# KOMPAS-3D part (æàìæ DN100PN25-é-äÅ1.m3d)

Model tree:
1. Объединить компоненты:1  (labels: СЕНС DN100PN25-В-ДП1)

Referenced files in D:\Савин\!СЕНСОР\3D для заказчика\!Новый перечень\СЕНС\5. СЕНС-В-ДП\DN100\: СЕНС DN100PN25-В-ДП1.a3d
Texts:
  СЕНС DN100PN25-В-ДП1
  ООО НПП Сенсор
